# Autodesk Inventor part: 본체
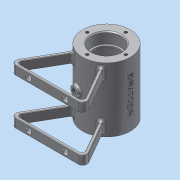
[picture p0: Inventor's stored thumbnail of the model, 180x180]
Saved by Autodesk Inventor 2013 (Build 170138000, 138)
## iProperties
Created: 2016-03
Part Number: 본체
Material: 알루미늄 6061
Document SubType Name: Modeling
Designer: Administrator
Mass: 211.864 g
Surface Area: 336.958 cm^2
Volume: 78.1787 cm^3
Density: 2.71 g/cm^3
Author: Administrator
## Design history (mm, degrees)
sketch "스케치1"
  geometry: C1 r 26 at (0, 0); 1 further point
  constraints: 1 centre point, 1 coincident
  dimensions: "d0" = 52 diameter of C1
extrude "돌출1" new body sketch "스케치1" stored distance "d1" = 70; taper "d2" = 0 deg
hole "구멍1" diameter "d5" = 28; stored, may be unused: countersink angle "d9" = 90 deg, drill point angle "d11" = 0 deg; dims "d3" = 10, "d4" = 10, "d6" = 6, "d7" = 32, "d8" = 12, "d10" = 14
hole "구멍2" diameter "d14" = 42; stored, may be unused: countersink angle "d18" = 90 deg, drill point angle "d20" = 0 deg; dims "d12" = 10, "d13" = 10, "d15" = 6, "d16" = 42, "d17" = 12, "d19" = 42
sketch "스케치2"
  geometry: C1 r 16 at (0, 0) reference; 1 further point
  constraints: 1 vertical alignment
  dimensions: "d21" = 21 distance of C1.centre point (0, 21)
hole "구멍3" sketch "스케치2" at (0, 21) diameter "d22" = 3.242; stored, may be unused: countersink angle "d26" = 90 deg, drill point angle "d28" = 118 deg; dims "d23" = 8, "d24" = 42, "d25" = 12, "d27" = 10
chamfer "모따기1" distance "d32" = 1; stored, may be unused: second distance "d33" = 2, angle "d34" = 45 deg
fillet "모깎기1" dims "d35" = 0.3
node "작업 평면1"
sketch "스케치4"
  geometry: L1 (-16.613, -20)-(-42.594, -65); L2 (-42.594, -65)-(42.594, -65); L3 (42.594, -65)-(16.613, -20); L4 (0, 0)-(0, -35.846); C1 r 16 at (0, 0) reference; C2 r 1.621 at (21, 0) reference; C3 r 1.621 at (0, -21) reference; C4 r 1.621 at (-21, 0) reference; C5 r 1.621 at (0, 21) reference; A1 r 26 centre (0, 0) between (-16.613, -20) and (16.613, -20) reference; 1 further point
  constraints: 8 end point, 2 point on circle, 1 equal length, 1 horizontal, 1 perpendicular
  dimensions: "d39" = 65 distance from line of point (0, 0) L2; "d40" = 30 deg angle of L1 L4; "d41" = 30 deg angle of L3 L4; "d42" = 45 distance from line of L3.end L2
extrude "돌출2" join sketch "스케치4" distance "d43" = 10; taper "d44" = 0 deg
sketch "스케치5"
  geometry: L1 (-16.613, -20)-(-42.594, -65) reference; L2 (-42.594, -65)-(42.594, -65) reference; L3 (42.594, -65)-(16.613, -20) reference; L4 (-37.398, -62)-(-14.183, -21.791); L5 (14.183, -21.791)-(37.398, -62); L6 (37.398, -62)-(-37.398, -62); A1 r 26 centre (0, 0) between (-16.613, -20) and (16.613, -20) reference; A2 r 29 centre (0, 0) between (-15.685, -24.392) and (15.685, -24.392)
  constraints: 6 end point, 4 point on circle, 2 point on line, 1 centre point
  dimensions: "d45" = 3 distance between parallel lines of L1 L4; "d68" = 3 distance between parallel lines of L3 L5; "d69" = 3 distance between parallel lines of L2 L6
extrude "돌출3" cut sketch "스케치5" distance "d46" = 10; taper "d47" = 0 deg
sketch "스케치6"
  geometry: L1 (0, 0)-(85.188, 0) reference; L2 (85.188, -10)-(0, -10) reference; L3 (42.594, -10)-(42.594, 0); 2 further points
  constraints: 2 end point, 2 midpoint
  dimensions: "d49" = 20 distance from line of L3 point (22.594, -5); "d50" = 5 distance from line of L2 point (22.594, -5)
node "작업 평면2"
sketch "스케치7"
  geometry: L1 (26, 35)-(-26, 35) reference; C1 r 5 at (0, 0); 1 further point
  constraints: 1 centre point, 1 coincident
  dimensions: "d52" = 10 diameter of C1
extrude "돌출4" join sketch "스케치7" stored distance "d53" = 3; taper "d54" = 0 deg
hole "구멍4" diameter "d57" = 5.188; stored, may be unused: countersink angle "d61" = 90 deg, drill point angle "d63" = 0 deg; dims "d55" = 10, "d56" = 10, "d58" = 6, "d59" = 4, "d60" = 2, "d62" = 8
fillet "모깎기3" dims "d64" = 5, "d65" = 3
fillet "모깎기4" dims "d66" = 0.5
fillet "모깎기5" dims "d67" = 0.5
fillet "모깎기6" dims "d70" = 3
fillet "모깎기7" dims "d74" = 2
hole "구멍5" sketch "스케치6" diameter "d75" = 6; stored, may be unused: countersink angle "d79" = 90 deg, drill point angle "d81" = 0 deg; dims "d76" = 6, "d77" = 4, "d78" = 2, "d80" = 8
node "작업 평면3"
sketch "스케치8"
  geometry: L1 (26, 35)-(-26, 35) reference; L2 (26, -35)-(26, 35) reference; 2 further points
  constraints: 1 other
  dimensions: "d88" = 35 distance from line of L1 point (0, 0); "d89" = 26 distance from line of L2 point (0, 0)
feature "엠보싱1" sketch "스케치8" dims "d90" = 0.5, "d91" = 0
fillet "모깎기9" dims "d93" = 3
node "솔리드1"
pattern_circular "원형 패턴1" dims angle "d30" = 360 deg
mirror "대칭1"
mirror "대칭2"
pattern_circular "원형 패턴2" dims angle "d72" = 165 deg
pattern_linear "직사각형 패턴1" dims "d84" = 40
node "절단 모서리 투영2"
other parameters: "d51" = 29
